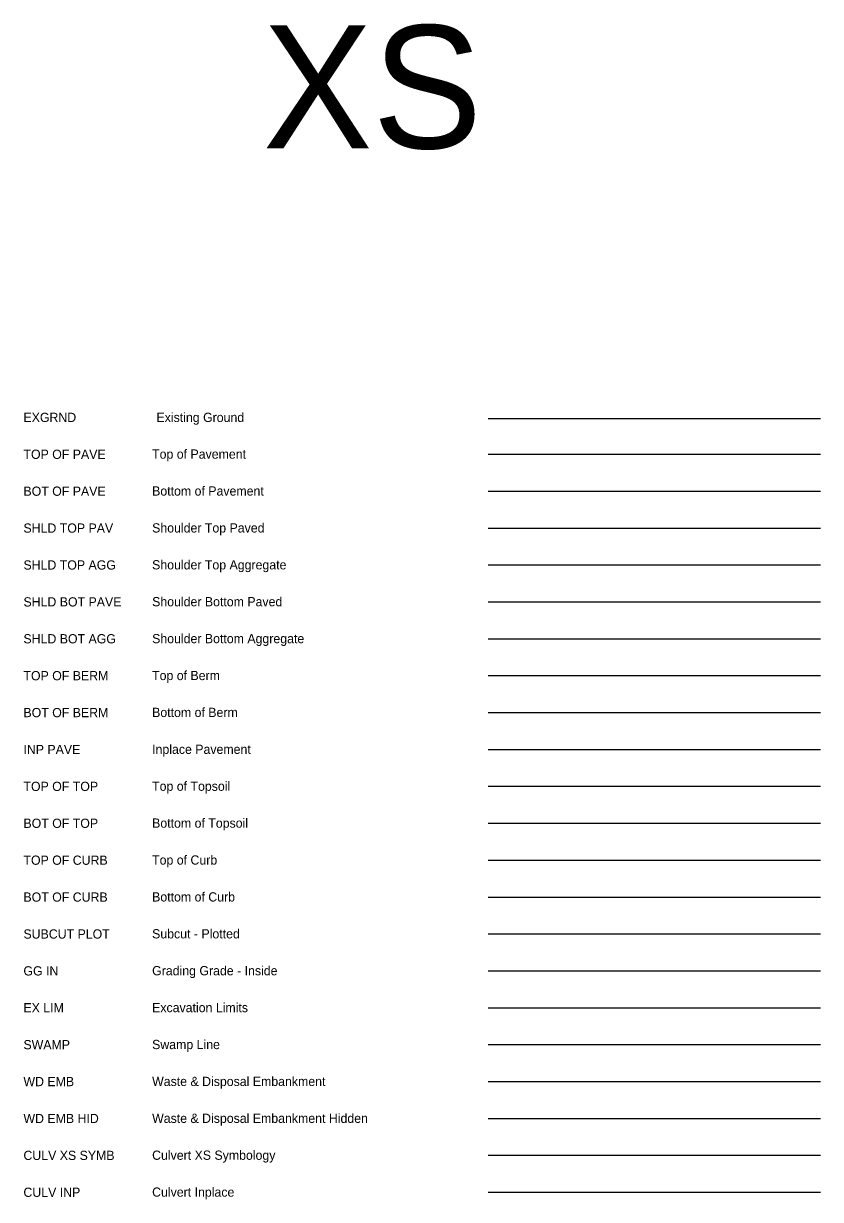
# Model space of a CAD drawing. Extents: x 2147712 to 2176316, y 2125036 to 2131746.
# Drawn here: x 2147712 to 2148360, y 2128679 to 2129635 of the extents above; entities that cross this region are included whole.
import ezdxf

# ---------------------------------------------------------------- set-up
doc = ezdxf.new("R2010")
doc.units = 0
for name, color, linetype in [('AGG HID', 7, 'Continuous'), ('BPFG CG BOT', 7, 'Continuous'), ('BPFG PAVE BOT', 7, 'Continuous'), ('BPFG SHLD BOT PAVE', 7, 'Continuous'), ('BPFG SWALK BOT', 7, 'Continuous'), ('Default', 7, 'Continuous'), ('DETAIL TXT', 7, 'Continuous'), ('EX LIM', 7, 'Continuous'), ('GRADE', 7, 'Continuous'), ('GRND INP', 7, 'Continuous'), ('PAVE INP', 7, 'Continuous'), ('PFG CG TOP', 7, 'Continuous'), ('PFG PAVE TOP', 7, 'Continuous'), ('PFG SHLD TOP', 7, 'Continuous'), ('PFG SWALK', 7, 'Continuous'), ('PFG TOPSOIL', 7, 'Continuous'), ('SUBCUT', 7, 'Continuous'), ('SWAMP EMBANK', 7, 'Continuous'), ('SWAMP EMBANK HID', 7, 'Continuous'), ('SWAMP LIN INP', 7, 'Continuous'), ('TOPSOIL BOT', 7, 'Continuous')]:
    doc.layers.add(name, color=color, linetype=linetype)

msp = doc.modelspace()

# ---------------------------------------------------------------- linework, layer by layer
at = {"layer": 'AGG HID'}
msp.add_line((2148089.77, 2129135.09), (2148360.17, 2129135.09), dxfattribs=at)
at = {"layer": 'BPFG CG BOT'}
msp.add_line((2148089.77, 2128925.1), (2148360.17, 2128925.1), dxfattribs=at)
at = {"layer": 'BPFG PAVE BOT'}
msp.add_line((2148089.77, 2129255.09), (2148360.17, 2129255.09), dxfattribs=at)
at = {"layer": 'BPFG SHLD BOT PAVE'}
msp.add_line((2148089.77, 2129165.09), (2148360.17, 2129165.09), dxfattribs=at)
at = {"layer": 'BPFG SWALK BOT'}
msp.add_line((2148089.77, 2129075.09), (2148360.17, 2129075.09), dxfattribs=at)
at = {"layer": 'Default'}
for p, q in [((2148089.77, 2128715.1), (2148360.17, 2128715.1)), ((2148089.77, 2128685.1), (2148360.17, 2128685.1))]:
    msp.add_line(p, q, dxfattribs=at)
at = {"layer": 'EX LIM'}
msp.add_line((2148089.77, 2128835.1), (2148360.17, 2128835.1), dxfattribs=at)
at = {"layer": 'GRADE'}
msp.add_line((2148089.77, 2128865.1), (2148360.17, 2128865.1), dxfattribs=at)
at = {"layer": 'GRND INP'}
msp.add_line((2148089.77, 2129314.14), (2148360.17, 2129314.14), dxfattribs=at)
at = {"layer": 'PAVE INP'}
msp.add_line((2148089.77, 2129045.09), (2148360.17, 2129045.09), dxfattribs=at)
at = {"layer": 'PFG CG TOP'}
msp.add_line((2148089.77, 2128955.1), (2148360.17, 2128955.1), dxfattribs=at)
at = {"layer": 'PFG PAVE TOP'}
msp.add_line((2148089.77, 2129285.09), (2148360.17, 2129285.09), dxfattribs=at)
at = {"layer": 'PFG SHLD TOP'}
for p, q in [((2148089.77, 2129225.09), (2148360.17, 2129225.09)), ((2148089.77, 2129195.09), (2148360.17, 2129195.09))]:
    msp.add_line(p, q, dxfattribs=at)
at = {"layer": 'PFG SWALK'}
msp.add_line((2148089.77, 2129105.09), (2148360.17, 2129105.09), dxfattribs=at)
at = {"layer": 'PFG TOPSOIL'}
msp.add_line((2148089.77, 2129015.09), (2148360.17, 2129015.09), dxfattribs=at)
at = {"layer": 'SUBCUT'}
msp.add_line((2148089.77, 2128895.1), (2148360.17, 2128895.1), dxfattribs=at)
at = {"layer": 'SWAMP EMBANK'}
msp.add_line((2148089.77, 2128775.1), (2148360.17, 2128775.1), dxfattribs=at)
at = {"layer": 'SWAMP EMBANK HID'}
msp.add_line((2148089.77, 2128745.1), (2148360.17, 2128745.1), dxfattribs=at)
at = {"layer": 'SWAMP LIN INP'}
msp.add_line((2148089.77, 2128805.1), (2148360.17, 2128805.1), dxfattribs=at)
at = {"layer": 'TOPSOIL BOT'}
msp.add_line((2148089.77, 2128985.09), (2148360.17, 2128985.09), dxfattribs=at)

# ---------------------------------------------------------------- texts
at = {"layer": 'DETAIL TXT'}
for s, height, p in [('XS', 100, (2147906.44, 2129533.76)), ('EXGRND', 7.5, (2147711.66, 2129311.29)), ('Existing Ground', 7.5, (2147819.89, 2129311.29)), ('TOP OF PAVE', 7.5, (2147711.66, 2129281.29)), ('Top of Pavement', 7.5, (2147816.35, 2129281.44)), ('BOT OF PAVE', 7.5, (2147711.66, 2129251.29)), ('Bottom of Pavement', 7.5, (2147816.35, 2129251.44)), ('SHLD TOP PAV', 7.5, (2147711.66, 2129221.29)), ('Shoulder Top Paved', 7.5, (2147816.35, 2129221.44)), ('SHLD TOP AGG', 7.5, (2147711.66, 2129191.29)), ('Shoulder Top Aggregate', 7.5, (2147816.35, 2129191.44)), ('SHLD BOT PAVE', 7.5, (2147711.66, 2129161.29)), ('Shoulder Bottom Paved', 7.5, (2147816.35, 2129161.44)), ('SHLD BOT AGG', 7.5, (2147711.66, 2129131.29)), ('Shoulder Bottom Aggregate', 7.5, (2147816.35, 2129131.44)), ('TOP OF BERM', 7.5, (2147711.66, 2129101.29)), ('Top of Berm', 7.5, (2147816.35, 2129101.44)), ('BOT OF BERM', 7.5, (2147711.66, 2129071.29)), ('Bottom of Berm', 7.5, (2147816.35, 2129071.44)), ('INP PAVE', 7.5, (2147711.66, 2129041.29)), ('Inplace Pavement', 7.5, (2147816.35, 2129041.44)), ('TOP OF TOP', 7.5, (2147711.66, 2129011.29)), ('Top of Topsoil', 7.5, (2147816.35, 2129011.44)), ('BOT OF TOP', 7.5, (2147711.66, 2128981.29)), ('Bottom of Topsoil', 7.5, (2147816.35, 2128981.44)), ('TOP OF CURB', 7.5, (2147711.66, 2128951.29)), ('Top of Curb', 7.5, (2147816.35, 2128951.44)), ('BOT OF CURB', 7.5, (2147711.66, 2128921.29)), ('Bottom of Curb', 7.5, (2147816.35, 2128921.44)), ('SUBCUT PLOT', 7.5, (2147711.66, 2128891.29)), ('Subcut - Plotted', 7.5, (2147816.35, 2128891.44)), ('GG IN', 7.5, (2147711.66, 2128861.29)), ('Grading Grade - Inside', 7.5, (2147816.35, 2128861.44)), ('EX LIM', 7.5, (2147711.66, 2128831.29)), ('Excavation Limits', 7.5, (2147816.35, 2128831.44)), ('SWAMP', 7.5, (2147711.66, 2128801.29)), ('Swamp Line', 7.5, (2147816.35, 2128801.44)), ('Waste & Disposal Embankment', 7.5, (2147816.35, 2128771.44)), ('WD EMB', 7.5, (2147711.66, 2128771.29)), ('WD EMB HID', 7.5, (2147711.66, 2128741.29)), ('Waste & Disposal Embankment Hidden', 7.5, (2147816.35, 2128741.44)), ('CULV XS SYMB', 7.5, (2147711.66, 2128711.29)), ('Culvert XS Symbology', 7.5, (2147816.35, 2128711.44)), ('CULV INP', 7.5, (2147711.66, 2128681.29)), ('Culvert Inplace', 7.5, (2147816.35, 2128681.44))]:
    msp.add_text(s, height=height, dxfattribs=at).set_placement(p)

doc.saveas('drawing.dxf')
